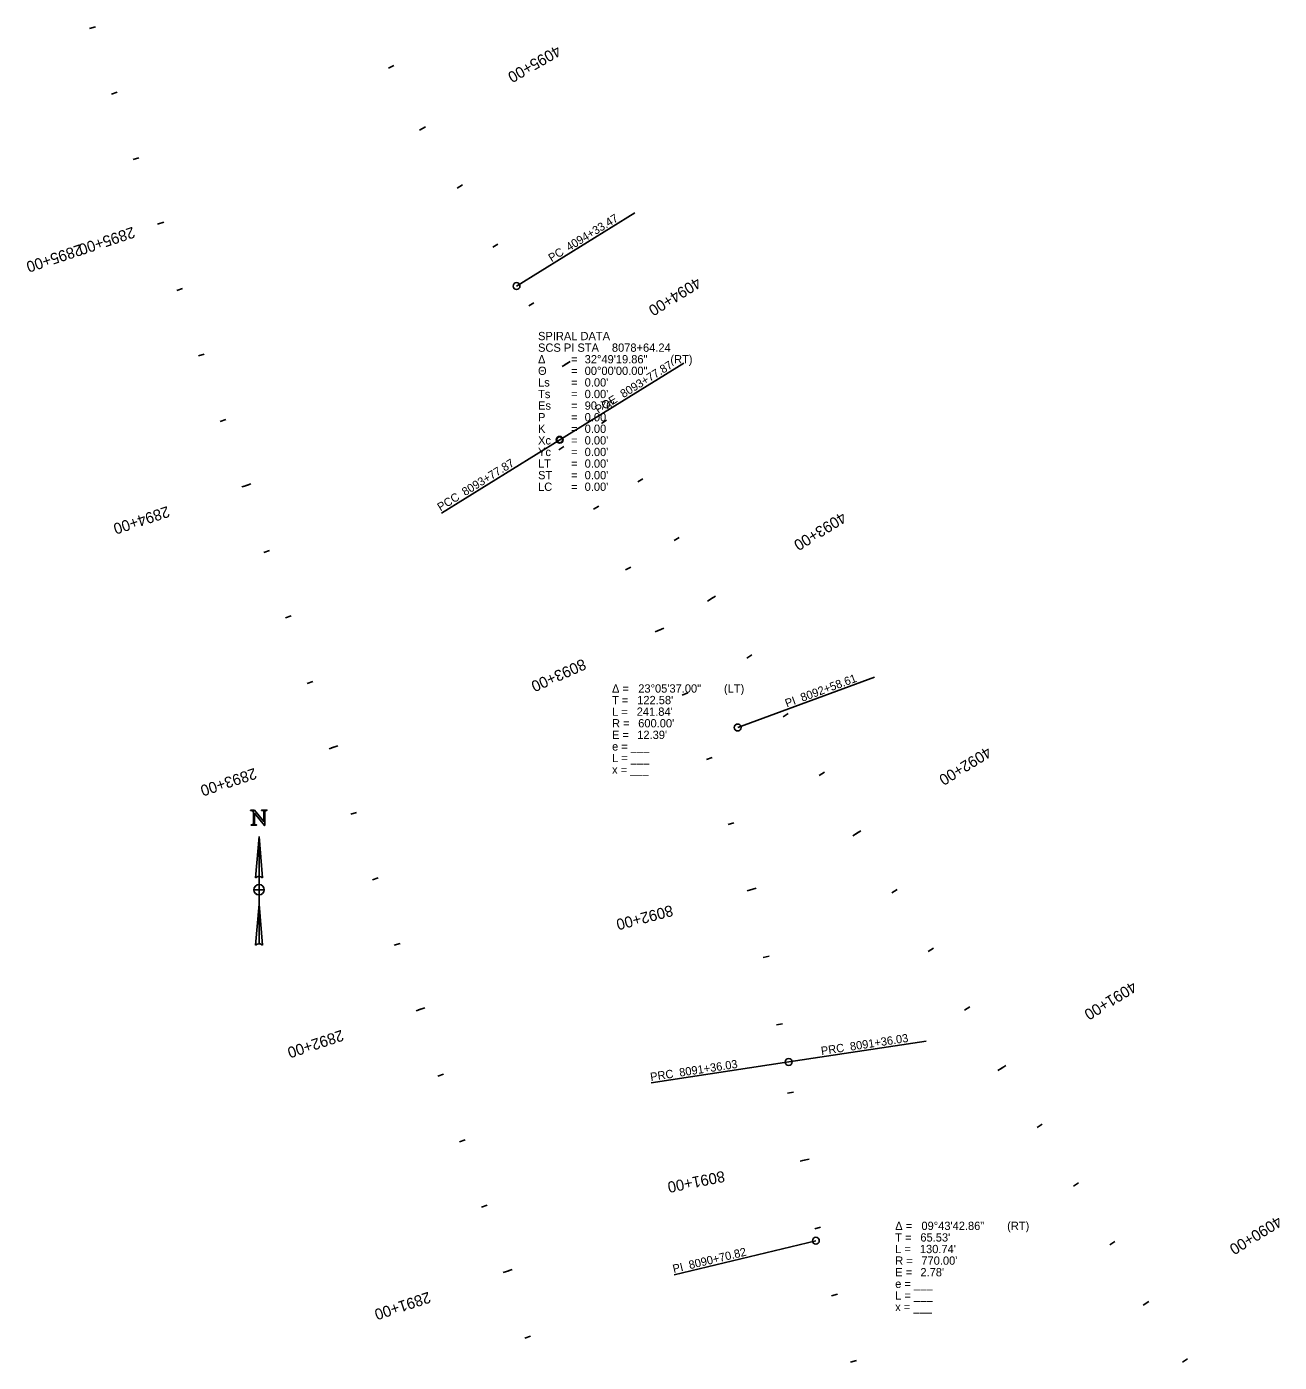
# Model space of a CAD drawing. Extents: x 16395645 to 16399055, y 7230557 to 7240583.
# Drawn here: x 16396906.8 to 16397360.6, y 7236330.6 to 7236814.5 of the extents above; entities that cross this region are included whole.
import ezdxf

# ---------------------------------------------------------------- set-up
doc = ezdxf.new("R2010")
doc.units = 0
for name, color, linetype in [('SheetGridMajor', 7, 'Continuous'), ('TextAlignment', 7, 'Continuous'), ('TextAlignmentLrg', 7, 'Continuous'), ('TextAlignmentSml', 7, 'Continuous')]:
    doc.layers.add(name, color=color, linetype=linetype)

msp = doc.modelspace()

# ---------------------------------------------------------------- linework, layer by layer
at = {"layer": 'SheetGridMajor'}
for p, q in [((16396990.96, 7236521.09), (16396989.66, 7236506.14)), ((16396990.96, 7236521.09), (16396992.27, 7236506.14)), ((16396990.96, 7236506.71), (16396990.96, 7236521.09)), ((16396990.96, 7236482.24), (16396990.96, 7236521.09)), ((16396990.96, 7236506.67), (16396990.96, 7236506.71)), ((16396990.96, 7236501.84), (16396989.09, 7236501.84)), ((16396992.84, 7236501.84), (16396989.09, 7236501.84)), ((16396990.96, 7236501.84), (16396990.96, 7236503.71)), ((16396992.84, 7236501.84), (16396990.96, 7236501.84)), ((16396990.96, 7236499.96), (16396990.96, 7236501.84)), ((16396990.96, 7236496.66), (16396989.66, 7236481.71)), ((16396990.96, 7236482.24), (16396990.96, 7236496.66)), ((16396990.96, 7236496.66), (16396992.27, 7236481.71))]:
    msp.add_line(p, q, dxfattribs=at)
for points in [[(16396987.83, 7236530.7), (16396989.31, 7236530.7), (16396992.68, 7236526.57), (16396992.68, 7236529.75)], [(16396987.83, 7236530.55), (16396987.83, 7236530.7)], [(16396988.91, 7236526.15), (16396988.91, 7236529.98)], [(16396993.04, 7236529.75), (16396993.04, 7236525.11), (16396992.89, 7236525.11), (16396989.27, 7236529.54), (16396989.27, 7236526.15)], [(16396992.09, 7236530.55), (16396991.9, 7236530.55), (16396991.9, 7236530.7), (16396993.81, 7236530.7), (16396993.81, 7236530.55), (16396993.62, 7236530.55)], [(16396989.85, 7236525.35), (16396990.04, 7236525.35), (16396990.04, 7236525.2), (16396988.14, 7236525.2), (16396988.14, 7236525.35), (16396988.33, 7236525.35)]]:
    msp.add_lwpolyline(points, dxfattribs=at)
for centre, start, end in [((16396990.96, 7236504.8), 45.7867, 134.2133), ((16396990.96, 7236504.8), 90, 134.2134), ((16396990.96, 7236501.84), 90, 89.4464), ((16396990.96, 7236501.84), 180, 270), ((16396990.96, 7236501.84), 360, 89.9989), ((16396990.96, 7236480.37), 45.7867, 134.2134), ((16396990.96, 7236480.37), 45.7867, 90)]:
    msp.add_arc(centre, 1.87, start, end, dxfattribs=at)
for points in [[(16396988.91, 7236529.98), (16396988.67, 7236530.26), (16396988.55, 7236530.35), (16396988.43, 7236530.44), (16396988.19, 7236530.51), (16396988.07, 7236530.55), (16396987.83, 7236530.55)], [(16396992.68, 7236529.75), (16396992.68, 7236530.25), (16396992.57, 7236530.38), (16396992.42, 7236530.55), (16396992.09, 7236530.55)], [(16396993.62, 7236530.55), (16396993.27, 7236530.55), (16396993.13, 7236530.34), (16396993.04, 7236530.21), (16396993.04, 7236529.75)], [(16396988.33, 7236525.35), (16396988.68, 7236525.35), (16396988.82, 7236525.56), (16396988.91, 7236525.69), (16396988.91, 7236526.15)], [(16396989.27, 7236526.15), (16396989.27, 7236525.64), (16396989.38, 7236525.52), (16396989.53, 7236525.35), (16396989.85, 7236525.35)]]:
    msp.add_open_spline(points, degree=3, dxfattribs=at)
at = {"layer": 'TextAlignment'}
for p, q in [((16397084.26, 7236720.56), (16397127.12, 7236747.08)), ((16397127.12, 7236747.08), (16397127.12, 7236747.08)), ((16397099.91, 7236664.86), (16397144.81, 7236692.64)), ((16397144.81, 7236692.64), (16397144.81, 7236692.64)), ((16397099.91, 7236664.86), (16397057.05, 7236638.34)), ((16397057.05, 7236638.34), (16397057.05, 7236638.34)), ((16397164.41, 7236560.62), (16397213.96, 7236578.85)), ((16397213.96, 7236578.85), (16397213.96, 7236578.85)), ((16397182.85, 7236439.43), (16397232.68, 7236447.01)), ((16397232.68, 7236447.01), (16397232.68, 7236447.01)), ((16397182.85, 7236439.43), (16397133.03, 7236431.85)), ((16397133.03, 7236431.85), (16397133.03, 7236431.85)), ((16397192.71, 7236374.65), (16397141.38, 7236362.3)), ((16397141.38, 7236362.3), (16397141.38, 7236362.3))]:
    msp.add_line(p, q, dxfattribs=at)
for centre, radius in [((16397084.26, 7236720.56), 1.25), ((16397099.91, 7236664.86), 1.25), ((16397099.91, 7236664.86), 1.07), ((16397164.41, 7236560.62), 1.25), ((16397182.85, 7236439.43), 1.25), ((16397182.85, 7236439.43), 1.25), ((16397192.71, 7236374.65), 1.25)]:
    msp.add_circle(centre, radius, dxfattribs=at)
at = {"layer": 'TextAlignmentLrg'}
for p, q in [((16397049.14, 7236777.09), (16397051.27, 7236778.31)), ((16396954.16, 7236742.98), (16396956.48, 7236743.76)), ((16397101.87, 7236692.09), (16397103.73, 7236693.24)), ((16396986.86, 7236648.47), (16396984.79, 7236647.78)), ((16397154.49, 7236607.06), (16397156.35, 7236608.21)), ((16397136.48, 7236596.17), (16397134.49, 7236595.27)), ((16397018.39, 7236553.57), (16397016.32, 7236552.89)), ((16397207.11, 7236522.02), (16397208.96, 7236523.17)), ((16397169.88, 7236502.04), (16397167.77, 7236501.48)), ((16397049.93, 7236458.68), (16397047.86, 7236457.99)), ((16397259.72, 7236436.98), (16397261.58, 7236438.13)), ((16397189.11, 7236403.95), (16397186.97, 7236403.52)), ((16397081.46, 7236363.78), (16397079.39, 7236363.09)), ((16397311.3, 7236351.3), (16397313.38, 7236352.59))]:
    msp.add_line(p, q, dxfattribs=at)
at = {"layer": 'TextAlignmentSml'}
for p, q in [((16396931.67, 7236814.54), (16396929.6, 7236813.85)), ((16397037.9, 7236799.47), (16397039.81, 7236800.53)), ((16396939.56, 7236790.82), (16396937.48, 7236790.13)), ((16397049.14, 7236777.09), (16397051.27, 7236778.31)), ((16396947.44, 7236767.09), (16396945.37, 7236766.41)), ((16397062.78, 7236756.1), (16397064.66, 7236757.21)), ((16396954.16, 7236742.98), (16396956.48, 7236743.76)), ((16397075.62, 7236734.65), (16397077.49, 7236735.78)), ((16396963.21, 7236719.65), (16396961.13, 7236718.96)), ((16397088.72, 7236713.35), (16397090.58, 7236714.5)), ((16396971.09, 7236695.92), (16396969.02, 7236695.23)), ((16397100.83, 7236691.45), (16397102.91, 7236692.74)), ((16396978.97, 7236672.2), (16396976.9, 7236671.51)), ((16397115.03, 7236670.83), (16397116.89, 7236671.98)), ((16397101.42, 7236662.41), (16397099.55, 7236661.27)), ((16397128.18, 7236649.58), (16397130.04, 7236650.72)), ((16396985.7, 7236648.09), (16396988.02, 7236648.86)), ((16397114.02, 7236640.83), (16397112.11, 7236639.76)), ((16397141.34, 7236628.32), (16397143.19, 7236629.46)), ((16396994.74, 7236624.75), (16396992.67, 7236624.06)), ((16397125.71, 7236618.73), (16397123.76, 7236617.75)), ((16397153.45, 7236606.41), (16397155.53, 7236607.7)), ((16397002.63, 7236601.02), (16397000.55, 7236600.33)), ((16397135.36, 7236595.67), (16397137.59, 7236596.67)), ((16397167.64, 7236585.8), (16397169.5, 7236586.95)), ((16397010.51, 7236577.3), (16397008.44, 7236576.61)), ((16397146.29, 7236573.18), (16397144.27, 7236572.36)), ((16397180.8, 7236564.54), (16397182.66, 7236565.69)), ((16397017.23, 7236553.19), (16397019.55, 7236553.96)), ((16397155.14, 7236549.8), (16397153.08, 7236549.07)), ((16397193.95, 7236543.28), (16397195.81, 7236544.43)), ((16397026.28, 7236529.85), (16397024.2, 7236529.16)), ((16397163.01, 7236526.07), (16397160.92, 7236525.43)), ((16397206.07, 7236521.37), (16397208.15, 7236522.66)), ((16397034.16, 7236506.13), (16397032.09, 7236505.44)), ((16397168.7, 7236501.72), (16397171.06, 7236502.35)), ((16397220.26, 7236500.76), (16397222.12, 7236501.91)), ((16397042.04, 7236482.4), (16397039.97, 7236481.71)), ((16397233.42, 7236479.5), (16397235.27, 7236480.65)), ((16397175.74, 7236477.74), (16397173.61, 7236477.27)), ((16397048.77, 7236458.29), (16397051.09, 7236459.06)), ((16397246.57, 7236458.24), (16397248.43, 7236459.39)), ((16397180.59, 7236453.21), (16397178.44, 7236452.83)), ((16397258.68, 7236436.34), (16397260.77, 7236437.62)), ((16397057.81, 7236434.95), (16397055.74, 7236434.26)), ((16397184.59, 7236428.53), (16397182.44, 7236428.17)), ((16397272.88, 7236415.72), (16397274.74, 7236416.87)), ((16397065.7, 7236411.23), (16397063.62, 7236410.54)), ((16397187.91, 7236403.71), (16397190.31, 7236404.19)), ((16397286.03, 7236394.46), (16397287.89, 7236395.61)), ((16397073.58, 7236387.5), (16397071.51, 7236386.82)), ((16397194.42, 7236379.52), (16397192.29, 7236379.02)), ((16397299.19, 7236373.2), (16397301.04, 7236374.35)), ((16397080.3, 7236363.39), (16397082.62, 7236364.17)), ((16397200.52, 7236355.27), (16397198.41, 7236354.71)), ((16397311.3, 7236351.3), (16397313.38, 7236352.59)), ((16397089.35, 7236340.06), (16397087.27, 7236339.37)), ((16397207.4, 7236331.24), (16397205.31, 7236330.61)), ((16397325.5, 7236330.68), (16397327.35, 7236331.83))]:
    msp.add_line(p, q, dxfattribs=at)

# ---------------------------------------------------------------- texts
at = {"layer": 'TextAlignment'}
for s, rotation, p in [('4094+33.47', 31.747, (16397103.3, 7236733.12)), ('PC', 31.747, (16397096.95, 7236729.19)), ('8093+77.87', 31.747, (16397123, 7236679.92)), ('POE ', 31.747, (16397113.85, 7236674.26)), ('8093+77.87', 31.747, (16397065.63, 7236644.42)), ('PCC', 31.747, (16397056.71, 7236638.9)), ('8092+58.61', 20.2002, (16397187.79, 7236569.92)), ('PI ', 20.2002, (16397182.18, 7236567.86)), ('8091+36.03', 8.6534, (16397205.3, 7236443.51)), ('PRC', 8.6534, (16397194.78, 7236441.91)), ('PRC', 8.6534, (16397132.93, 7236432.5)), ('8091+36.03', 8.6534, (16397143.45, 7236434.1)), ('8090+70.82', 13.5177, (16397147.04, 7236364.34)), ('PI ', 13.5177, (16397141.22, 7236362.94))]:
    msp.add_text(s, height=3, rotation=rotation, dxfattribs=at).set_placement(p)
for s, p in [('SPIRAL DATA', (16397092.05, 7236700.96)), ('SCS PI STA ', (16397092.05, 7236696.76)), ('8078+64.24', (16397118.81, 7236696.76)), ('Δ', (16397092.05, 7236692.56)), ('= ', (16397104.05, 7236692.56)), ('32°49\'19.86"', (16397108.94, 7236692.56)), (' (RT)', (16397138.88, 7236692.56)), ('Θ ', (16397092.05, 7236688.36)), ('= ', (16397104.05, 7236688.36)), ('00°00\'00.00"', (16397108.94, 7236688.36)), ('Ls', (16397092.05, 7236684.16)), ('= ', (16397104.05, 7236684.16)), ("0.00'", (16397108.94, 7236684.16)), ('Ts', (16397092.05, 7236679.96)), ('Es', (16397092.05, 7236675.76)), ('= ', (16397104.05, 7236679.96)), ("0.00'", (16397108.94, 7236679.96)), ("90.76'", (16397108.94, 7236675.76)), ('P', (16397092.05, 7236671.56)), ('= ', (16397104.05, 7236675.76)), ('0.00', (16397108.94, 7236671.56)), ('K', (16397092.05, 7236667.36)), ('= ', (16397104.05, 7236671.56)), ('= ', (16397104.05, 7236667.36)), ('0.00', (16397108.94, 7236667.36)), ('Xc', (16397092.05, 7236663.16)), ('= ', (16397104.05, 7236663.16)), ("0.00'", (16397108.94, 7236663.16)), ('Yc', (16397092.05, 7236658.96)), ('= ', (16397104.05, 7236658.96)), ("0.00'", (16397108.94, 7236658.96)), ('LT', (16397092.05, 7236654.76)), ('= ', (16397104.05, 7236654.76)), ("0.00'", (16397108.94, 7236654.76)), ('ST ', (16397092.05, 7236650.56)), ('= ', (16397104.05, 7236650.56)), ("0.00'", (16397108.94, 7236650.56)), ('LC', (16397092.05, 7236646.36)), ('= ', (16397104.05, 7236646.36)), ("0.00'", (16397108.94, 7236646.36)), ('Δ = ', (16397118.86, 7236573.26)), ('23°05\'37.00"', (16397128.36, 7236573.26)), (' (LT)', (16397158.3, 7236573.26)), ('T = ', (16397118.86, 7236569.06)), ('L = ', (16397118.86, 7236564.86)), ("241.84'", (16397127.8, 7236564.86)), ("122.58'", (16397127.98, 7236569.06)), ('R = ', (16397118.86, 7236560.66)), ("600.00'", (16397128.34, 7236560.66)), ('E = ', (16397118.86, 7236556.46)), ("12.39'", (16397127.99, 7236556.46)), ('e = ___ ', (16397118.86, 7236552.26)), ('L = ___', (16397118.86, 7236548.06)), ('x = ___', (16397118.86, 7236543.86)), ('Δ = ', (16397221.45, 7236378.55)), ('09°43\'42.86"', (16397230.95, 7236378.55)), (' (RT)', (16397260.89, 7236378.55)), ('T = ', (16397221.45, 7236374.35)), ("65.53'", (16397230.57, 7236374.35)), ('L = ', (16397221.45, 7236370.15)), ('R = ', (16397221.45, 7236365.95)), ("130.74'", (16397230.39, 7236370.15)), ("770.00'", (16397230.93, 7236365.95)), ('E = ', (16397221.45, 7236361.75)), ("2.78'", (16397230.58, 7236361.75)), ('e = ___ ', (16397221.45, 7236357.55)), ('L = ___', (16397221.45, 7236353.35)), ('x = ___', (16397221.45, 7236349.15))]:
    msp.add_text(s, height=3, dxfattribs=at).set_placement(p)
at = {"layer": 'TextAlignmentLrg'}
for s, rotation, p in [('4095+00', 209.8411, (16397098.91, 7236807.96)), ('2895+00', 198.382, (16396945.2, 7236742.12)), ('4090+00', 211.747, (16397360.02, 7236383.8))]:
    msp.add_text(s, height=4.008, rotation=rotation, dxfattribs=at).set_placement(p)
at = {"layer": 'TextAlignmentSml'}
for s, rotation, p in [('4095+00', 209.8411, (16397098.91, 7236807.96)), ('2895+00', 198.382, (16396926.22, 7236735.81)), ('4094+00', 211.747, (16397149.55, 7236723.95)), ('2894+00', 198.382, (16396957.76, 7236640.91)), ('4093+00', 211.747, (16397202.17, 7236638.91)), ('8093+00', 204.3111, (16397108.31, 7236585.65)), ('4092+00', 211.747, (16397254.78, 7236553.87)), ('2893+00', 198.382, (16396989.29, 7236546.02)), ('8092+00', 194.7618, (16397140.36, 7236496.33)), ('4091+00', 211.747, (16397307.4, 7236468.84)), ('2892+00', 198.382, (16397020.83, 7236451.12)), ('8091+00', 191.3346, (16397159.3, 7236400.01)), ('4090+00', 211.747, (16397360.02, 7236383.8)), ('2891+00', 198.382, (16397052.36, 7236356.22))]:
    msp.add_text(s, height=4.008, rotation=rotation, dxfattribs=at).set_placement(p)

doc.saveas('drawing.dxf')
